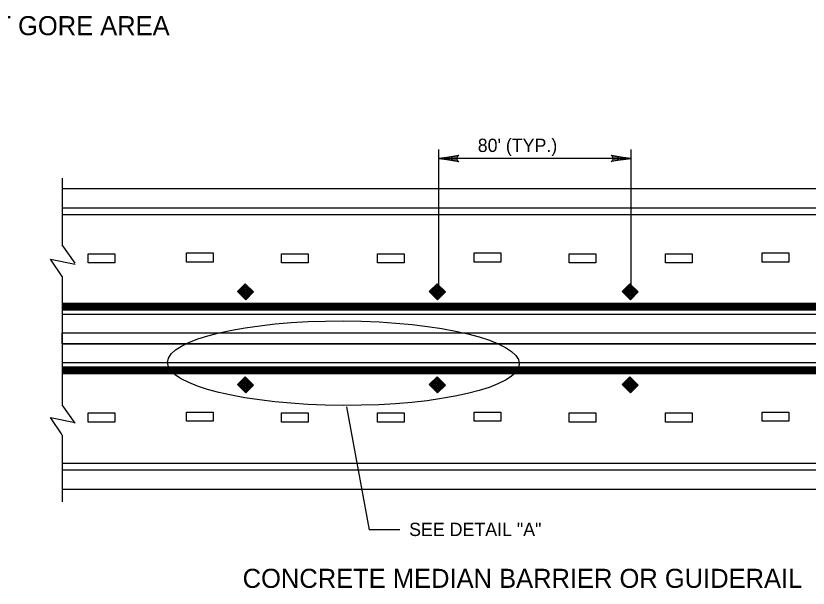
# Model space of a CAD drawing. Extents: x 639362 to 641108, y 298458 to 299646.
# Drawn here: x 639652.3 to 639830.9, y 299351.7 to 299480.8 of the extents above; entities that cross this region are included whole.
import ezdxf

# ---------------------------------------------------------------- set-up
doc = ezdxf.new("R2010")
doc.units = 0
doc.layers.add('2', color=7, linetype='Continuous')

msp = doc.modelspace()

# ---------------------------------------------------------------- linework, layer by layer
at = {"layer": '2'}
for p, q in [((639747.61, 299420.13), (639747.61, 299450.63)), ((639791.05, 299419.91), (639791.05, 299450.63)), ((639791.05, 299448.63), (639747.61, 299448.63)), ((639662.67, 299444.2), (639662.67, 299428.91)), ((639662.67, 299441.83), (639897.17, 299441.83)), ((639662.67, 299437.48), (639897.17, 299437.48)), ((639662.67, 299435.98), (639897.17, 299435.98)), ((639665.62, 299425), (639662.67, 299429.14)), ((639668.56, 299425.06), (639668.56, 299427.12)), ((639668.56, 299427.12), (639674.57, 299427.12)), ((639674.57, 299427.12), (639674.57, 299425.06)), ((639690.75, 299425.24), (639690.75, 299427.31)), ((639690.75, 299427.31), (639696.76, 299427.31)), ((639696.76, 299427.31), (639696.76, 299425.24)), ((639712.2, 299425.06), (639712.2, 299427.12)), ((639712.2, 299427.12), (639718.21, 299427.12)), ((639718.21, 299427.12), (639718.21, 299425.06)), ((639733.83, 299425.06), (639733.83, 299427.12)), ((639733.83, 299427.12), (639739.84, 299427.12)), ((639739.84, 299427.12), (639739.84, 299425.06)), ((639755.61, 299425.24), (639755.61, 299427.31)), ((639755.61, 299427.31), (639761.62, 299427.31)), ((639761.62, 299427.31), (639761.62, 299425.24)), ((639777.06, 299425.06), (639777.06, 299427.12)), ((639777.06, 299427.12), (639783.08, 299427.12)), ((639783.08, 299427.12), (639783.08, 299425.06)), ((639798.78, 299425.06), (639798.78, 299427.12)), ((639798.78, 299427.12), (639804.8, 299427.12)), ((639804.8, 299427.12), (639804.8, 299425.06)), ((639820.59, 299425.24), (639820.59, 299427.31)), ((639820.59, 299427.31), (639826.61, 299427.31)), ((639826.61, 299427.31), (639826.61, 299425.24)), ((639662.67, 299422.04), (639660.09, 299425.91)), ((639660.09, 299425.91), (639665.62, 299424.78)), ((639696.76, 299425.24), (639690.75, 299425.24)), ((639761.62, 299425.24), (639755.61, 299425.24)), ((639826.61, 299425.24), (639820.59, 299425.24)), ((639674.57, 299425.06), (639668.56, 299425.06)), ((639718.21, 299425.06), (639712.2, 299425.06)), ((639739.84, 299425.06), (639733.83, 299425.06)), ((639783.08, 299425.06), (639777.06, 299425.06)), ((639804.8, 299425.06), (639798.78, 299425.06)), ((639662.67, 299422.04), (639662.67, 299404.25)), ((639702.24, 299418.63), (639704.01, 299420.39)), ((639702.47, 299418.66), (639703.97, 299420.17)), ((639702.72, 299418.67), (639703.97, 299419.92)), ((639703.97, 299420.17), (639705.66, 299418.48)), ((639703.97, 299419.92), (639705.42, 299418.48)), ((639704.01, 299420.39), (639705.88, 299418.52)), ((639745.5, 299418.63), (639747.27, 299420.39)), ((639745.73, 299418.66), (639747.23, 299420.17)), ((639745.98, 299418.67), (639747.23, 299419.92)), ((639747.23, 299420.17), (639748.93, 299418.48)), ((639747.23, 299419.92), (639748.68, 299418.48)), ((639747.27, 299420.39), (639749.15, 299418.52)), ((639788.98, 299418.63), (639790.74, 299420.39)), ((639789.2, 299418.66), (639790.7, 299420.17)), ((639789.45, 299418.67), (639790.71, 299419.92)), ((639790.7, 299420.17), (639792.4, 299418.48)), ((639790.71, 299419.92), (639792.15, 299418.48)), ((639790.74, 299420.39), (639792.62, 299418.52)), ((639704.12, 299416.75), (639702.24, 299418.63)), ((639704.16, 299416.97), (639702.47, 299418.66)), ((639704.16, 299417.22), (639702.72, 299418.67)), ((639702.97, 299418.66), (639703.97, 299419.67)), ((639704.16, 299417.47), (639702.97, 299418.66)), ((639703.22, 299418.67), (639703.97, 299419.42)), ((639704.16, 299417.73), (639703.22, 299418.67)), ((639703.47, 299418.67), (639703.97, 299419.17)), ((639704.16, 299417.98), (639703.47, 299418.67)), ((639703.72, 299418.67), (639703.97, 299418.92)), ((639704.16, 299418.23), (639703.72, 299418.67)), ((639703.97, 299419.67), (639705.16, 299418.48)), ((639703.97, 299419.42), (639704.91, 299418.48)), ((639703.97, 299419.17), (639704.66, 299418.48)), ((639703.97, 299418.92), (639704.41, 299418.48)), ((639703.97, 299418.67), (639704.16, 299418.48)), ((639705.88, 299418.52), (639704.12, 299416.75)), ((639705.66, 299418.48), (639704.16, 299416.97)), ((639705.42, 299418.48), (639704.16, 299417.22)), ((639705.16, 299418.48), (639704.16, 299417.47)), ((639704.91, 299418.48), (639704.16, 299417.73)), ((639704.66, 299418.48), (639704.16, 299417.98)), ((639704.41, 299418.48), (639704.16, 299418.23)), ((639747.38, 299416.75), (639745.5, 299418.63)), ((639747.42, 299416.97), (639745.73, 299418.66)), ((639747.42, 299417.22), (639745.98, 299418.67)), ((639746.23, 299418.66), (639747.23, 299419.67)), ((639747.42, 299417.47), (639746.23, 299418.66)), ((639746.48, 299418.67), (639747.23, 299419.42)), ((639747.42, 299417.73), (639746.48, 299418.67)), ((639746.73, 299418.67), (639747.23, 299419.17)), ((639747.42, 299417.98), (639746.73, 299418.67)), ((639746.98, 299418.67), (639747.23, 299418.92)), ((639747.42, 299418.23), (639746.98, 299418.67)), ((639747.23, 299419.67), (639748.43, 299418.48)), ((639747.23, 299419.42), (639748.17, 299418.48)), ((639747.23, 299419.17), (639747.92, 299418.48)), ((639747.23, 299418.92), (639747.67, 299418.48)), ((639747.23, 299418.67), (639747.42, 299418.48)), ((639749.15, 299418.52), (639747.38, 299416.75)), ((639748.93, 299418.48), (639747.42, 299416.97)), ((639748.68, 299418.48), (639747.42, 299417.22)), ((639748.43, 299418.48), (639747.42, 299417.47)), ((639748.17, 299418.48), (639747.42, 299417.73)), ((639747.92, 299418.48), (639747.42, 299417.98)), ((639747.67, 299418.48), (639747.42, 299418.23)), ((639790.85, 299416.75), (639788.98, 299418.63)), ((639790.89, 299416.97), (639789.2, 299418.66)), ((639790.89, 299417.22), (639789.45, 299418.67)), ((639789.7, 299418.66), (639790.71, 299419.67)), ((639790.89, 299417.47), (639789.7, 299418.66)), ((639789.95, 299418.67), (639790.71, 299419.42)), ((639790.89, 299417.73), (639789.95, 299418.67)), ((639790.2, 299418.67), (639790.71, 299419.17)), ((639790.89, 299417.98), (639790.2, 299418.67)), ((639790.45, 299418.67), (639790.7, 299418.92)), ((639790.89, 299418.23), (639790.45, 299418.67)), ((639790.7, 299418.92), (639791.14, 299418.48)), ((639790.7, 299418.67), (639790.89, 299418.48)), ((639790.71, 299419.67), (639791.9, 299418.48)), ((639790.71, 299419.42), (639791.65, 299418.48)), ((639790.71, 299419.17), (639791.39, 299418.48)), ((639792.62, 299418.52), (639790.85, 299416.75)), ((639792.4, 299418.48), (639790.89, 299416.97)), ((639792.15, 299418.48), (639790.89, 299417.22)), ((639791.9, 299418.48), (639790.89, 299417.47)), ((639791.65, 299418.48), (639790.89, 299417.73)), ((639791.39, 299418.48), (639790.89, 299417.98)), ((639791.14, 299418.48), (639790.89, 299418.23)), ((639662.67, 299415.97), (639897.17, 299415.97)), ((639662.67, 299415.82), (639897.17, 299415.82)), ((639662.67, 299415.67), (639897.17, 299415.67)), ((639662.67, 299415.52), (639897.17, 299415.52)), ((639662.67, 299415.37), (639897.17, 299415.37)), ((639662.67, 299415.22), (639897.17, 299415.22)), ((639662.67, 299415.07), (639897.17, 299415.07)), ((639662.67, 299414.92), (639897.17, 299414.92)), ((639662.67, 299414.77), (639897.17, 299414.77)), ((639662.67, 299414.62), (639897.17, 299414.62)), ((639662.67, 299414.47), (639897.17, 299414.47)), ((639662.67, 299413.5), (639897.17, 299413.5)), ((639662.67, 299409.32), (639897.17, 299409.32)), ((639662.67, 299406.82), (639897.17, 299406.82)), ((639662.67, 299406.75), (639662.67, 299393.18)), ((639662.67, 299402.65), (639897.17, 299402.65)), ((639662.67, 299401.67), (639897.17, 299401.67)), ((639662.67, 299401.67), (639897.17, 299401.67)), ((639662.67, 299401.67), (639897.17, 299401.67)), ((639662.67, 299401.52), (639897.17, 299401.52)), ((639662.67, 299401.37), (639897.17, 299401.37)), ((639662.67, 299401.22), (639897.17, 299401.22)), ((639662.67, 299401.07), (639897.17, 299401.07)), ((639662.67, 299400.92), (639897.17, 299400.92)), ((639662.67, 299400.77), (639897.17, 299400.77)), ((639662.67, 299400.62), (639897.17, 299400.62)), ((639662.67, 299400.47), (639897.17, 299400.47)), ((639662.67, 299400.32), (639897.17, 299400.32)), ((639662.67, 299400.17), (639897.17, 299400.17)), ((639702.24, 299397.65), (639704.01, 299399.42)), ((639702.47, 299397.69), (639703.97, 299399.19)), ((639702.72, 299397.69), (639703.97, 299398.94)), ((639702.97, 299397.69), (639703.97, 299398.69)), ((639703.22, 299397.69), (639703.97, 299398.44)), ((639703.97, 299399.19), (639705.66, 299397.5)), ((639703.97, 299398.94), (639705.42, 299397.5)), ((639703.97, 299398.69), (639705.16, 299397.5)), ((639703.97, 299398.44), (639704.91, 299397.5)), ((639704.01, 299399.42), (639705.88, 299397.54)), ((639745.5, 299397.65), (639747.27, 299399.42)), ((639745.73, 299397.69), (639747.23, 299399.19)), ((639745.98, 299397.69), (639747.23, 299398.94)), ((639746.23, 299397.69), (639747.23, 299398.69)), ((639746.48, 299397.69), (639747.23, 299398.44)), ((639747.23, 299399.19), (639748.93, 299397.5)), ((639747.23, 299398.94), (639748.68, 299397.5)), ((639747.23, 299398.69), (639748.43, 299397.5)), ((639747.23, 299398.44), (639748.17, 299397.5)), ((639747.27, 299399.42), (639749.15, 299397.54)), ((639788.98, 299397.65), (639790.74, 299399.42)), ((639789.2, 299397.69), (639790.7, 299399.19)), ((639789.45, 299397.69), (639790.71, 299398.94)), ((639789.7, 299397.69), (639790.71, 299398.69)), ((639789.95, 299397.69), (639790.71, 299398.44)), ((639790.7, 299399.19), (639792.4, 299397.5)), ((639790.71, 299398.94), (639792.15, 299397.5)), ((639790.71, 299398.69), (639791.9, 299397.5)), ((639790.71, 299398.44), (639791.65, 299397.5)), ((639790.74, 299399.42), (639792.62, 299397.54)), ((639704.12, 299395.77), (639702.24, 299397.65)), ((639704.16, 299395.99), (639702.47, 299397.69)), ((639704.16, 299396.25), (639702.72, 299397.69)), ((639704.16, 299396.5), (639702.97, 299397.69)), ((639704.16, 299396.75), (639703.22, 299397.69)), ((639703.47, 299397.69), (639703.97, 299398.19)), ((639704.16, 299397), (639703.47, 299397.69)), ((639703.72, 299397.69), (639703.97, 299397.94)), ((639704.16, 299397.25), (639703.72, 299397.69)), ((639703.97, 299398.19), (639704.66, 299397.5)), ((639703.97, 299397.94), (639704.41, 299397.5)), ((639703.97, 299397.69), (639704.16, 299397.5)), ((639705.88, 299397.54), (639704.12, 299395.77)), ((639705.66, 299397.5), (639704.16, 299395.99)), ((639705.42, 299397.5), (639704.16, 299396.25)), ((639705.16, 299397.5), (639704.16, 299396.5)), ((639704.91, 299397.5), (639704.16, 299396.75)), ((639704.66, 299397.5), (639704.16, 299397)), ((639704.41, 299397.5), (639704.16, 299397.25)), ((639747.38, 299395.77), (639745.5, 299397.65)), ((639747.42, 299395.99), (639745.73, 299397.69)), ((639747.42, 299396.25), (639745.98, 299397.69)), ((639747.42, 299396.5), (639746.23, 299397.69)), ((639747.42, 299396.75), (639746.48, 299397.69)), ((639746.73, 299397.69), (639747.23, 299398.19)), ((639747.42, 299397), (639746.73, 299397.69)), ((639746.98, 299397.69), (639747.23, 299397.94)), ((639747.42, 299397.25), (639746.98, 299397.69)), ((639747.23, 299398.19), (639747.92, 299397.5)), ((639747.23, 299397.94), (639747.67, 299397.5)), ((639747.23, 299397.69), (639747.42, 299397.5)), ((639749.15, 299397.54), (639747.38, 299395.77)), ((639748.93, 299397.5), (639747.42, 299395.99)), ((639748.68, 299397.5), (639747.42, 299396.25)), ((639748.43, 299397.5), (639747.42, 299396.5)), ((639748.17, 299397.5), (639747.42, 299396.75)), ((639747.92, 299397.5), (639747.42, 299397)), ((639747.67, 299397.5), (639747.42, 299397.25)), ((639790.85, 299395.77), (639788.98, 299397.65)), ((639790.89, 299395.99), (639789.2, 299397.69)), ((639790.89, 299396.25), (639789.45, 299397.69)), ((639790.89, 299396.5), (639789.7, 299397.69)), ((639790.89, 299396.75), (639789.95, 299397.69)), ((639790.2, 299397.69), (639790.71, 299398.19)), ((639790.89, 299397), (639790.2, 299397.69)), ((639790.45, 299397.69), (639790.7, 299397.94)), ((639790.89, 299397.25), (639790.45, 299397.69)), ((639790.7, 299397.94), (639791.14, 299397.5)), ((639790.7, 299397.69), (639790.89, 299397.5)), ((639790.71, 299398.19), (639791.39, 299397.5)), ((639792.62, 299397.54), (639790.85, 299395.77)), ((639792.4, 299397.5), (639790.89, 299395.99)), ((639792.15, 299397.5), (639790.89, 299396.25)), ((639791.9, 299397.5), (639790.89, 299396.5)), ((639791.65, 299397.5), (639790.89, 299396.75)), ((639791.39, 299397.5), (639790.89, 299397)), ((639791.14, 299397.5), (639790.89, 299397.25)), ((639665.62, 299388.97), (639662.67, 299393.1)), ((639690.75, 299389.37), (639690.75, 299391.43)), ((639690.75, 299391.43), (639696.76, 299391.43)), ((639696.76, 299391.43), (639696.76, 299389.37)), ((639726.8, 299392.59), (639731.95, 299364.88)), ((639755.61, 299389.37), (639755.61, 299391.43)), ((639755.61, 299391.43), (639761.62, 299391.43)), ((639761.62, 299391.43), (639761.62, 299389.37)), ((639820.59, 299389.37), (639820.59, 299391.43)), ((639820.59, 299391.43), (639826.61, 299391.43)), ((639826.61, 299391.43), (639826.61, 299389.37)), ((639662.67, 299386.31), (639660.09, 299390.18)), ((639660.09, 299390.18), (639665.62, 299389.05)), ((639668.56, 299389.18), (639668.56, 299391.25)), ((639668.56, 299391.25), (639674.57, 299391.25)), ((639674.57, 299391.25), (639674.57, 299389.18)), ((639712.2, 299389.18), (639712.2, 299391.25)), ((639712.2, 299391.25), (639718.21, 299391.25)), ((639718.21, 299391.25), (639718.21, 299389.18)), ((639733.83, 299389.18), (639733.83, 299391.25)), ((639733.83, 299391.25), (639739.84, 299391.25)), ((639739.84, 299391.25), (639739.84, 299389.18)), ((639777.06, 299389.18), (639777.06, 299391.25)), ((639777.06, 299391.25), (639783.08, 299391.25)), ((639783.08, 299391.25), (639783.08, 299389.18)), ((639798.78, 299389.18), (639798.78, 299391.25)), ((639798.78, 299391.25), (639804.8, 299391.25)), ((639804.8, 299391.25), (639804.8, 299389.18)), ((639674.57, 299389.18), (639668.56, 299389.18)), ((639696.76, 299389.37), (639690.75, 299389.37)), ((639718.21, 299389.18), (639712.2, 299389.18)), ((639739.84, 299389.18), (639733.83, 299389.18)), ((639761.62, 299389.37), (639755.61, 299389.37)), ((639783.08, 299389.18), (639777.06, 299389.18)), ((639804.8, 299389.18), (639798.78, 299389.18)), ((639826.61, 299389.37), (639820.59, 299389.37)), ((639662.67, 299386.24), (639662.67, 299371.17)), ((639662.67, 299379.94), (639897.17, 299379.94)), ((639662.67, 299378.44), (639897.17, 299378.44)), ((639662.67, 299374.09), (639897.17, 299374.09)), ((639738.85, 299364.88), (639731.95, 299364.88))]:
    msp.add_line(p, q, dxfattribs=at)
for points in [[(639751.93, 299448.08), (639751.77, 299448.4), (639747.61, 299448.63), (639751.93, 299448.08), (639752.15, 299447.89), (639747.61, 299448.63), (639751.77, 299448.83), (639751.92, 299449.14), (639747.61, 299448.63), (639752.15, 299449.35), (639751.92, 299449.14)], [(639786.73, 299449.17), (639786.89, 299448.85), (639791.05, 299448.63), (639786.73, 299449.17), (639786.51, 299449.36), (639791.05, 299448.63), (639786.9, 299448.42), (639786.75, 299448.11), (639791.05, 299448.63), (639786.51, 299447.9), (639786.75, 299448.11)]]:
    msp.add_lwpolyline(points, dxfattribs=at)
msp.add_lwpolyline([(639662.67, 299409.32), (639897.17, 299409.32), (639897.17, 299406.82), (639662.67, 299406.82)], close=True, dxfattribs=at)
msp.add_ellipse((639726.13, 299402.46), major_axis=(39.66, -0.17), ratio=0.240157, dxfattribs=at)

# ---------------------------------------------------------------- texts
for s, height, p in [('EXIT GORE AREA', 4.3, (639638.38, 299476.41)), ("80' (TYP.)", 3, (639756.42, 299450.08)), ('SEE DETAIL "A"', 3, (639740.95, 299363.49)), ('CONCRETE MEDIAN BARRIER OR GUIDERAIL', 4.3, (639703.41, 299351.8))]:
    msp.add_text(s, height=height, dxfattribs=at).set_placement(p)

doc.saveas('drawing.dxf')
